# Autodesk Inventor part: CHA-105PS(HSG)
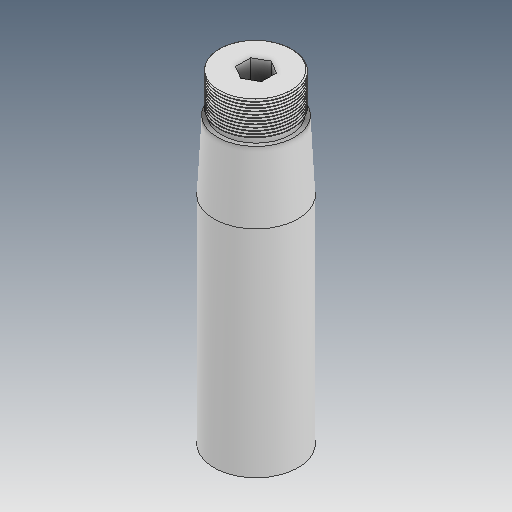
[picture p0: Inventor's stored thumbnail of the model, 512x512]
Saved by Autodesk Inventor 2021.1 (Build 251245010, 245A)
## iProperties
Created: 2021-05
Part Number: CHA-105PS(HSG)
Material: Ogólny
Document SubType Name: Modeling
Designer: user
Density: 1 g/cm^3
Appearance: Domyślna
Author: user
Revision Number: ÈÎºÎ
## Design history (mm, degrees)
feature "ÇÐ³ý-Ðý×ª2"
node "Bryła1"
